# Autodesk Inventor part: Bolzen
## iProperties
Shininess: 64.0
Length Units: 11269
Angle Units: 11279
Time Units: 11290
Mass Units: 11283
Length Display Precision: 3
Angle Display Precision: 2
Compacted: True
Part Number: Bolzen
Document SubType Name: Modeling
Created: 2005-08
Material: Standard
Designer: Kumpf
Density: 0.0
Volumn: 0.0
Area: 0.0
PropertySet Name: Model Information
Control State: 0
Master: False
Checked Out: False
Author: Kumpf
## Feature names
1. Extrusion1
2. Extrusion2
3. Extrusion3
4. Extrusion4
5. Extrusion5
6. Fase1 [Chamfer]
7. Fase2 [Chamfer]
